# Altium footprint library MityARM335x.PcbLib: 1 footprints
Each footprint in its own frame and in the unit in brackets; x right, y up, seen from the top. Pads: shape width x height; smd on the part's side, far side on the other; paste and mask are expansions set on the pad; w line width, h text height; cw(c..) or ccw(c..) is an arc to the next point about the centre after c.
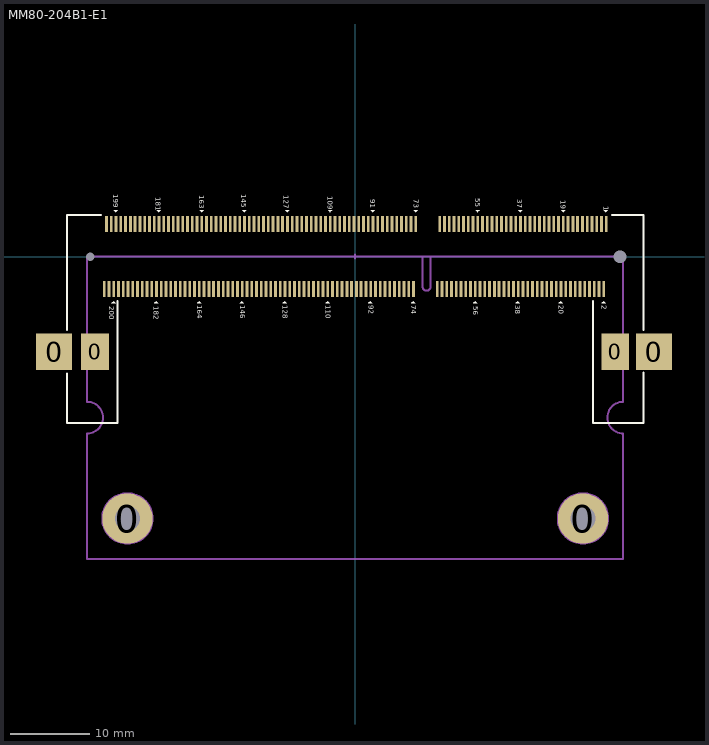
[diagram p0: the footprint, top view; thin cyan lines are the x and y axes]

## MM80-204B1-E1 [mm] "CONN SODIMM DDR3 204POS R/A SMD"
height 1.9
pads (212):
  rect 4.5x4.6 smd: 0(-37.973,-11.995) 0(37.673,-11.995)
  round 0 hole 1.1 unplated: 0(-33.4,0.005)
  rect 3.5x4.6 smd: 0(-32.8,-11.995) 0(32.8,-11.995)
  round 6.35 / inner round 4.191 / far side round 6.35 hole 3.175: 0(-28.72,-33.025)
  round 6.35 hole 3.175: 0(28.72,-33.025)
  round 0 hole 1.6 unplated: 0(33.4,0.005)
  rect 0.35x2 smd: 1(31.65,4.105) 2(31.35,-4.095) 3(31.05,4.105) 4(30.75,-4.095) 5(30.45,4.105) 6(30.15,-4.095) 7(29.85,4.105) 8(29.55,-4.095) 9(29.25,4.105) 10(28.95,-4.095) 11(28.65,4.105) 12(28.35,-4.095) 13(28.05,4.105) 14(27.75,-4.095) 15(27.45,4.105) 16(27.15,-4.095) 17(26.85,4.105) 18(26.55,-4.095) 19(26.25,4.105) 20(25.95,-4.095) 21(25.65,4.105) 22(25.35,-4.095) 23(25.05,4.105) 24(24.75,-4.095) 25(24.45,4.105) 26(24.15,-4.095) 27(23.85,4.105) 28(23.55,-4.095) 29(23.25,4.105) 30(22.95,-4.095) 31(22.65,4.105) 32(22.35,-4.095) 33(22.05,4.105) 34(21.75,-4.095) 35(21.45,4.105) 36(21.15,-4.095) 37(20.85,4.105) 38(20.55,-4.095) 39(20.25,4.105) 40(19.95,-4.095) 41(19.65,4.105) 42(19.35,-4.095) 43(19.05,4.105) 44(18.75,-4.095) 45(18.45,4.105) 46(18.15,-4.095) 47(17.85,4.105) 48(17.55,-4.095) 49(17.25,4.105) 50(16.95,-4.095) 51(16.65,4.105) 52(16.35,-4.095) 53(16.05,4.105) 54(15.75,-4.095) 55(15.45,4.105) 56(15.15,-4.095) 57(14.85,4.105) 58(14.55,-4.095) 59(14.25,4.105) 60(13.95,-4.095) 61(13.65,4.105) 62(13.35,-4.095) 63(13.05,4.105) 64(12.75,-4.095) 65(12.45,4.105) 66(12.15,-4.095) 67(11.85,4.105) 68(11.55,-4.095) 69(11.25,4.105) 70(10.95,-4.095) 71(10.65,4.105) 72(10.35,-4.095) 73(7.65,4.105) 74(7.35,-4.095) 75(7.05,4.105) 76(6.75,-4.095) 77(6.45,4.105) 78(6.15,-4.095) 79(5.85,4.105) 80(5.55,-4.095) 81(5.25,4.105) 82(4.95,-4.095) 83(4.65,4.105) 84(4.35,-4.095) 85(4.05,4.105) 86(3.75,-4.095) 87(3.45,4.105) 88(3.15,-4.095) 89(2.85,4.105) 90(2.55,-4.095) 91(2.25,4.105) 92(1.95,-4.095) 93(1.65,4.105) 94(1.35,-4.095) 95(1.05,4.105) 96(0.75,-4.095) 97(0.45,4.105) 98(0.15,-4.095) 99(-0.15,4.105) 100(-0.45,-4.095) 101(-0.75,4.105) 102(-1.05,-4.095) 103(-1.35,4.105) 104(-1.65,-4.095) 105(-1.95,4.105) 106(-2.25,-4.095) 107(-2.55,4.105) 108(-2.85,-4.095) 109(-3.15,4.105) 110(-3.45,-4.095) 111(-3.75,4.105) 112(-4.05,-4.095) 113(-4.35,4.105) 114(-4.65,-4.095) 115(-4.95,4.105) 116(-5.25,-4.095) 117(-5.55,4.105) 118(-5.85,-4.095) 119(-6.15,4.105) 120(-6.45,-4.095) 121(-6.75,4.105) 122(-7.05,-4.095) 123(-7.35,4.105) 124(-7.65,-4.095) 125(-7.95,4.105) 126(-8.25,-4.095) 127(-8.55,4.105) 128(-8.85,-4.095) 129(-9.15,4.105) 130(-9.45,-4.095) 131(-9.75,4.105) 132(-10.05,-4.095) 133(-10.35,4.105) 134(-10.65,-4.095) 135(-10.95,4.105) 136(-11.25,-4.095) 137(-11.55,4.105) 138(-11.85,-4.095) 139(-12.15,4.105) 140(-12.45,-4.095) 141(-12.75,4.105) 142(-13.05,-4.095) 143(-13.35,4.105) 144(-13.65,-4.095) 145(-13.95,4.105) 146(-14.25,-4.095) 147(-14.55,4.105) 148(-14.85,-4.095) 149(-15.15,4.105) 150(-15.45,-4.095) 151(-15.75,4.105) 152(-16.05,-4.095) 153(-16.35,4.105) 154(-16.65,-4.095) 155(-16.95,4.105) 156(-17.25,-4.095) 157(-17.55,4.105) 158(-17.85,-4.095) 159(-18.15,4.105) 160(-18.45,-4.095) 161(-18.75,4.105) 162(-19.05,-4.095) 163(-19.35,4.105) 164(-19.65,-4.095) 165(-19.95,4.105) 166(-20.25,-4.095) 167(-20.55,4.105) 168(-20.85,-4.095) 169(-21.15,4.105) 170(-21.45,-4.095) 171(-21.75,4.105) 172(-22.05,-4.095) 173(-22.35,4.105) 174(-22.65,-4.095) 175(-22.95,4.105) 176(-23.25,-4.095) 177(-23.55,4.105) 178(-23.85,-4.095) 179(-24.15,4.105) 180(-24.45,-4.095) 181(-24.75,4.105) 182(-25.05,-4.095) 183(-25.35,4.105) 184(-25.65,-4.095) 185(-25.95,4.105) 186(-26.25,-4.095) 187(-26.55,4.105) 188(-26.85,-4.095) 189(-27.15,4.105) 190(-27.45,-4.095) 191(-27.75,4.105) 192(-28.05,-4.095) 193(-28.35,4.105) 194(-28.65,-4.095) 195(-28.95,4.105) 196(-29.25,-4.095) 197(-29.55,4.105) 198(-29.85,-4.095) 199(-30.15,4.105) 200(-30.45,-4.095) 201(-30.75,4.105) 202(-31.05,-4.095) 203(-31.35,4.105) 204(-31.65,-4.095)
Top Overlay:
  region: 31.325,-5.591 31.075,-5.841 31.069,-5.845 31.577,-5.845 31.323,-5.591
  region: 25.925,-5.591 25.675,-5.841 25.669,-5.845 26.177,-5.845 25.923,-5.591
  region: 20.525,-5.591 20.275,-5.841 20.269,-5.845 20.777,-5.845 20.523,-5.591
  region: 15.125,-5.591 14.875,-5.841 14.869,-5.845 15.377,-5.845 15.123,-5.591
  region: 7.325,-5.591 7.075,-5.841 7.069,-5.845 7.577,-5.845 7.323,-5.591
  region: 1.925,-5.591 1.675,-5.841 1.669,-5.845 2.177,-5.845 1.923,-5.591
  region: -3.475,-5.591 -3.725,-5.841 -3.731,-5.845 -3.223,-5.845 -3.477,-5.591
  region: -8.875,-5.591 -9.125,-5.841 -9.131,-5.845 -8.623,-5.845 -8.877,-5.591
  region: -14.275,-5.591 -14.525,-5.841 -14.531,-5.845 -14.023,-5.845 -14.277,-5.591
  region: -19.675,-5.591 -19.925,-5.841 -19.931,-5.845 -19.423,-5.845 -19.677,-5.591
  region: -25.075,-5.591 -25.325,-5.841 -25.331,-5.845 -24.823,-5.845 -25.077,-5.591
  region: -30.475,-5.591 -30.725,-5.841 -30.731,-5.845 -30.223,-5.845 -30.477,-5.591
  region: -30.175,5.601 -30.425,5.851 -30.431,5.855 -29.923,5.855 -30.177,5.601
  region: -24.775,5.601 -25.025,5.851 -25.031,5.855 -24.523,5.855 -24.777,5.601
  region: -19.375,5.601 -19.625,5.851 -19.631,5.855 -19.123,5.855 -19.377,5.601
  region: -13.975,5.601 -14.225,5.851 -14.231,5.855 -13.723,5.855 -13.977,5.601
  region: -8.575,5.601 -8.825,5.851 -8.831,5.855 -8.323,5.855 -8.577,5.601
  region: -3.175,5.601 -3.425,5.851 -3.431,5.855 -2.923,5.855 -3.177,5.601
  region: 2.225,5.601 1.975,5.851 1.969,5.855 2.477,5.855 2.223,5.601
  region: 7.625,5.601 7.375,5.851 7.369,5.855 7.877,5.855 7.623,5.601
  region: 15.425,5.601 15.175,5.851 15.169,5.855 15.677,5.855 15.423,5.601
  region: 20.825,5.601 20.575,5.851 20.569,5.855 21.077,5.855 20.823,5.601
  region: 26.225,5.601 25.975,5.851 25.969,5.855 26.477,5.855 26.223,5.601
  region: 31.625,5.601 31.375,5.851 31.369,5.855 31.877,5.855 31.623,5.601
  lines w0.254: -36.35,-14.732 -36.35,-20.995 -30,-20.995 -30,-5.588 ; -36.35,-9.271 -36.35,5.237 -32.034,5.237 ; 30,-5.588 30,-20.995 36.35,-20.995 36.35,-14.605 ; 32.415,5.237 36.35,5.237 36.35,-9.271
  text "20" at 25.684,-6.099 h0.64
  text "2" at 31.084,-6.099 h0.64
  text "38" at 20.193,-6.096 h0.64
  text "56" at 14.859,-6.223 h0.64
  text "74" at 7.084,-6.099 h0.64
  text "92" at 1.684,-6.099 h0.64
  text "110" at -3.716,-6.099 h0.64
  text "128" at -9.116,-6.099 h0.64
  text "146" at -14.516,-6.099 h0.64
  text "164" at -19.916,-6.099 h0.64
  text "182" at -25.4,-6.223 h0.64
  text "200" at -30.988,-6.223 h0.64
  text "199" at -30.48,7.874 h0.64
  text "181" at -25.146,7.493 h0.64
  text "163" at -19.685,7.747 h0.64
  text "145" at -14.351,7.874 h0.64
  text "127" at -9.017,7.747 h0.64
  text "73" at 7.366,7.239 h0.64
  text "55" at 15.113,7.366 h0.64
  text "37" at 20.447,7.239 h0.64
  text "1" at 31.369,6.35 h0.64
  text "19" at 25.908,7.112 h0.64
  text "91" at 1.905,7.239 h0.64
  text "109" at -3.429,7.62 h0.64
Mechanical 1:
  lines w0.254: -33.8,0.005 17.05,0.005 33.8,0.005 ; -29.355,-33.025 -28.085,-33.025 ; -28.72,-33.65 -28.72,-32.38 ; -0.254,0.005 0.254,0.005 ; 0,-0.249 0,0.259 ; 28.085,-33.025 29.355,-33.025 ; 28.72,-33.65 28.72,-32.38 ; 33.8,-22.295 33.8,-38.1 -33.8,-38.1 -33.8,-22.295 ccw(c-33.799,-20.295) -33.799,-18.295 -33.799,0 8.501,0 8.501,-3.795 ccw(c9.001,-3.795) 9.501,-3.795 9.501,0 33.801,0 33.801,-18.295 ccw(c33.801,-20.295) 33.801,-22.295
  text "MityARM-335x outline" at -10.895,-36.154 h1.27
Mechanical 2:
  lines w0.254: -31.895,-33.015 ccw(c-28.72,-33.015) -28.72,-36.19 ccw(c-28.72,-33.015) -25.545,-33.015 ccw(c-28.72,-33.015) -28.72,-29.84 ccw(c-28.72,-33.015) -31.895,-33.015 ; 25.545,-33.015 cw(c28.72,-33.015) 28.72,-29.84 cw(c28.72,-33.015) 31.895,-33.015 cw(c28.72,-33.015) 28.72,-36.19 cw(c28.72,-33.015) 25.545,-33.015
3D body: height 6.5, standoff 1.97, extent -33.8,-38.1 33.8,0
3D body: height 5.5, standoff -0.65, extent -35.823,-21.523 35.777,5.017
